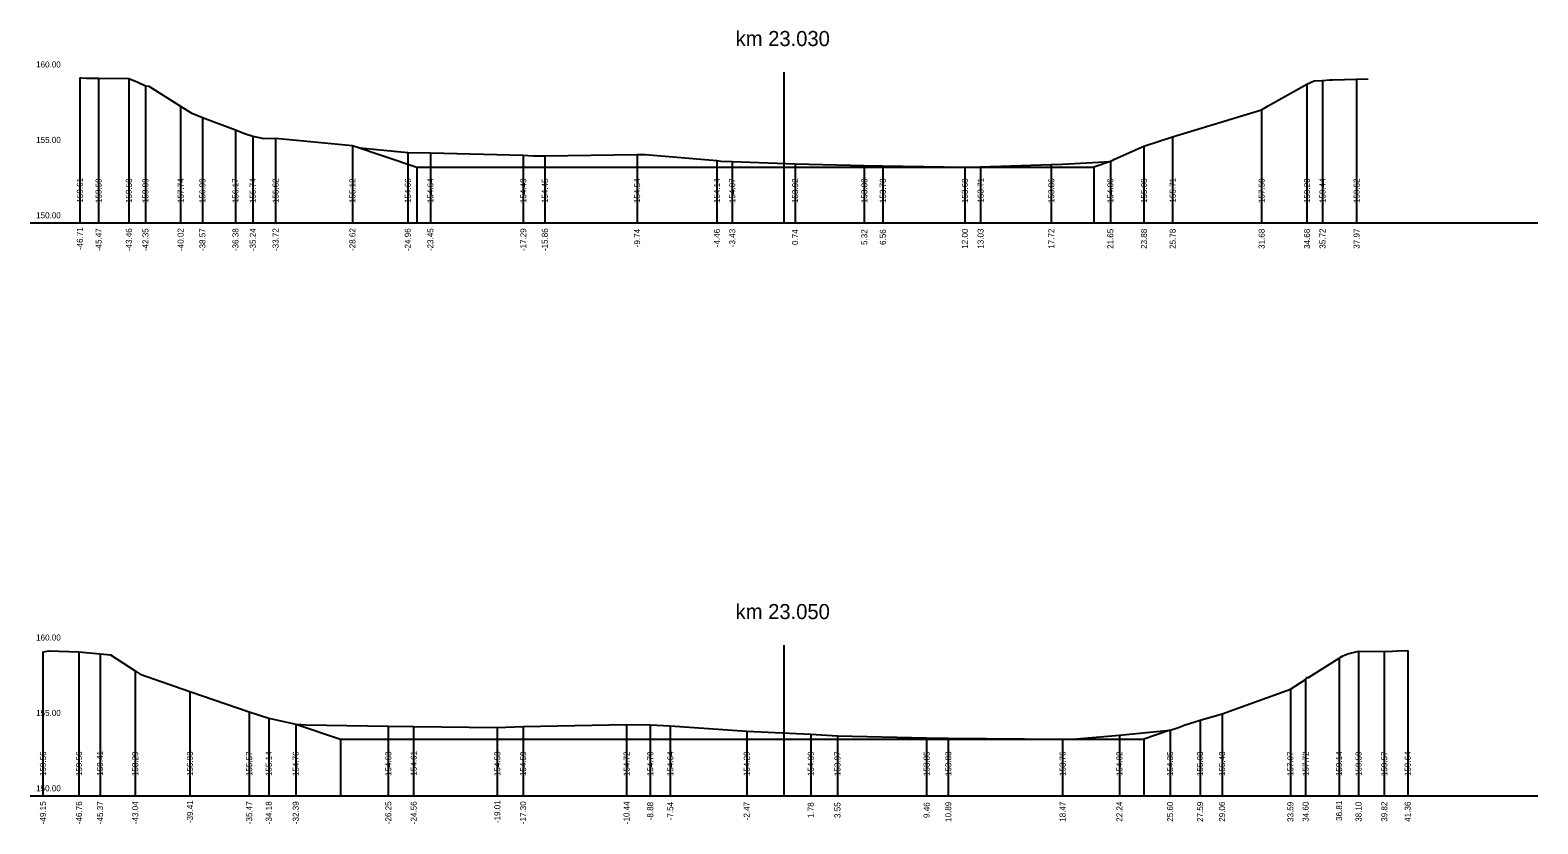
# Model space of a CAD drawing. Extents: x -582678 to -581845, y -1210354 to -1210235.
# Drawn here: x -582165.4 to -582065.4, y -1210306.7 to -1210254.1 of the extents above; entities that cross this region are included whole.
import ezdxf

# ---------------------------------------------------------------- set-up
doc = ezdxf.new("R2010")
doc.units = 0
for name, color, linetype in [('_N_osa', 7, 'Continuous'), ('_N_pomocná', 7, 'Continuous'), ('_N_tučná', 7, 'Continuous'), ('_S_popis', 7, 'Continuous'), ('_S_popis_oprav!', 7, 'Continuous'), ('_S_tenká', 7, 'Continuous'), ('_S_velmi_tenká', 7, 'Continuous')]:
    doc.layers.add(name, color=color, linetype=linetype)

msp = doc.modelspace()

# ---------------------------------------------------------------- linework, layer by layer
at = {"layer": '_N_osa'}
for p, q in [((-582115.45, -1210256.87), (-582115.45, -1210266.87)), ((-582115.45, -1210294.87), (-582115.45, -1210304.87))]:
    msp.add_line(p, q, dxfattribs=at)
at = {"layer": '_N_pomocná'}
for p, q in [((-582139.8, -1210263.17), (-582139.8, -1210266.87)), ((-582094.89, -1210263.17), (-582094.89, -1210266.87)), ((-582144.87, -1210301.1), (-582144.87, -1210304.87)), ((-582091.57, -1210301.1), (-582091.57, -1210304.87))]:
    msp.add_line(p, q, dxfattribs=at)
at = {"layer": '_N_tučná'}
for p, q in [((-582144.07, -1210261.75), (-582139.8, -1210263.17)), ((-582093.8, -1210262.81), (-582094.89, -1210263.17)), ((-582147.83, -1210300.11), (-582144.87, -1210301.1)), ((-582089.84, -1210300.52), (-582091.57, -1210301.1))]:
    msp.add_line(p, q, dxfattribs=at)
for points in [[(-582139.8, -1210263.17), (-582094.89, -1210263.17)], [(-582144.87, -1210301.1), (-582091.57, -1210301.1)]]:
    msp.add_lwpolyline(points, dxfattribs=at)
at = {"layer": '_S_tenká'}
for p, q in [((-582165.45, -1210266.87), (-582065.45, -1210266.87)), ((-582165.45, -1210304.87), (-582065.45, -1210304.87))]:
    msp.add_line(p, q, dxfattribs=at)
for points in [[(-582162.15, -1210257.25), (-582162.07, -1210257.26), (-582161.71, -1210257.27), (-582161.34, -1210257.27), (-582160.91, -1210257.28), (-582158.9, -1210257.29), (-582158.3, -1210257.55), (-582157.8, -1210257.78), (-582157.58, -1210257.81), (-582155.47, -1210259.13), (-582154.87, -1210259.5), (-582154.77, -1210259.58), (-582154.02, -1210259.88), (-582151.83, -1210260.7), (-582151.22, -1210260.94), (-582150.68, -1210261.12), (-582149.94, -1210261.27), (-582149.17, -1210261.25), (-582144.07, -1210261.75), (-582143.57, -1210261.9), (-582140.4, -1210262.2), (-582138.9, -1210262.23), (-582132.74, -1210262.38), (-582132.05, -1210262.43), (-582131.31, -1210262.42), (-582125.19, -1210262.33), (-582124.66, -1210262.35), (-582119.9, -1210262.73), (-582119.63, -1210262.78), (-582118.88, -1210262.8), (-582114.71, -1210262.95), (-582110.12, -1210263.07), (-582108.89, -1210263.09), (-582103.45, -1210263.19), (-582102.41, -1210263.16), (-582097.72, -1210263), (-582096.98, -1210262.98), (-582093.8, -1210262.81), (-582093.52, -1210262.64), (-582091.57, -1210261.79), (-582089.67, -1210261.16), (-582083.77, -1210259.37), (-582083.33, -1210259.11), (-582080.76, -1210257.67), (-582080.28, -1210257.46), (-582079.73, -1210257.43), (-582079.26, -1210257.39), (-582079.06, -1210257.38), (-582077.47, -1210257.35), (-582076.7, -1210257.32)], [(-582164.6, -1210295.31), (-582164.2, -1210295.26), (-582162.21, -1210295.31), (-582160.81, -1210295.46), (-582160.12, -1210295.52), (-582158.48, -1210296.58), (-582158.15, -1210296.8), (-582154.85, -1210297.94), (-582150.92, -1210299.3), (-582149.62, -1210299.72), (-582147.83, -1210300.11), (-582147.16, -1210300.17), (-582141.69, -1210300.24), (-582140.01, -1210300.26), (-582134.46, -1210300.34), (-582132.75, -1210300.28), (-582125.89, -1210300.14), (-582124.32, -1210300.17), (-582122.99, -1210300.23), (-582117.92, -1210300.58), (-582113.67, -1210300.78), (-582111.9, -1210300.9), (-582105.99, -1210301.02), (-582104.55, -1210301.04), (-582096.97, -1210301.11), (-582096.61, -1210301.11), (-582096.28, -1210301.11), (-582093.2, -1210300.84), (-582089.84, -1210300.52), (-582089.28, -1210300.33), (-582088.9, -1210300.18), (-582087.85, -1210299.84), (-582086.39, -1210299.44), (-582081.86, -1210297.79), (-582080.85, -1210297.15), (-582080.77, -1210297.03), (-582080.65, -1210297.02), (-582078.63, -1210295.73), (-582078.39, -1210295.58), (-582078.04, -1210295.45), (-582077.34, -1210295.28), (-582075.63, -1210295.3), (-582075.08, -1210295.28), (-582074.77, -1210295.25), (-582074.08, -1210295.23)]]:
    msp.add_lwpolyline(points, dxfattribs=at)
at = {"layer": '_S_velmi_tenká'}
for points in [[(-582162.15, -1210257.25), (-582162.15, -1210266.87), (-582162.15, -1210266.87), (-582162.15, -1210266.87)], [(-582160.91, -1210257.28), (-582160.91, -1210266.87), (-582160.91, -1210266.87), (-582160.91, -1210266.87)], [(-582158.9, -1210257.29), (-582158.9, -1210266.87), (-582158.9, -1210266.87), (-582158.9, -1210266.87)], [(-582157.8, -1210257.78), (-582157.8, -1210266.87), (-582157.8, -1210266.87), (-582157.8, -1210266.87)], [(-582080.76, -1210257.67), (-582080.76, -1210266.87), (-582080.76, -1210266.87), (-582080.76, -1210266.87)], [(-582079.73, -1210257.43), (-582079.73, -1210266.87), (-582079.73, -1210266.87), (-582079.73, -1210266.87)], [(-582077.47, -1210257.35), (-582077.47, -1210266.87), (-582077.47, -1210266.87), (-582077.47, -1210266.87)], [(-582155.47, -1210259.13), (-582155.47, -1210266.87), (-582155.47, -1210266.87), (-582155.47, -1210266.87)], [(-582154.02, -1210259.88), (-582154.02, -1210266.87), (-582154.02, -1210266.87), (-582154.02, -1210266.87)], [(-582083.77, -1210259.37), (-582083.77, -1210266.87), (-582083.77, -1210266.87), (-582083.77, -1210266.87)], [(-582151.83, -1210260.7), (-582151.83, -1210266.87), (-582151.83, -1210266.87), (-582151.83, -1210266.87)], [(-582150.68, -1210261.12), (-582150.68, -1210266.87), (-582150.68, -1210266.87), (-582150.68, -1210266.87)], [(-582149.17, -1210261.25), (-582149.17, -1210266.87), (-582149.17, -1210266.87), (-582149.17, -1210266.87)], [(-582144.07, -1210261.75), (-582144.07, -1210266.87), (-582144.07, -1210266.87), (-582144.07, -1210266.87)], [(-582091.57, -1210261.79), (-582091.57, -1210266.87), (-582091.57, -1210266.87), (-582091.57, -1210266.87)], [(-582089.67, -1210261.16), (-582089.67, -1210266.87), (-582089.67, -1210266.87), (-582089.67, -1210266.87)], [(-582140.4, -1210262.2), (-582140.4, -1210266.87), (-582140.4, -1210266.87), (-582140.4, -1210266.87)], [(-582138.9, -1210262.23), (-582138.9, -1210266.87), (-582138.9, -1210266.87), (-582138.9, -1210266.87)], [(-582132.74, -1210262.38), (-582132.74, -1210266.87), (-582132.74, -1210266.87), (-582132.74, -1210266.87)], [(-582131.31, -1210262.42), (-582131.31, -1210266.87), (-582131.31, -1210266.87), (-582131.31, -1210266.87)], [(-582125.19, -1210262.33), (-582125.19, -1210266.87), (-582125.19, -1210266.87), (-582125.19, -1210266.87)], [(-582119.9, -1210262.73), (-582119.9, -1210266.87), (-582119.9, -1210266.87), (-582119.9, -1210266.87)], [(-582118.88, -1210262.8), (-582118.88, -1210266.87), (-582118.88, -1210266.87), (-582118.88, -1210266.87)], [(-582114.71, -1210262.95), (-582114.71, -1210266.87), (-582114.71, -1210266.87), (-582114.71, -1210266.87)], [(-582093.8, -1210262.81), (-582093.8, -1210266.87), (-582093.8, -1210266.87), (-582093.8, -1210266.87)], [(-582110.12, -1210263.07), (-582110.12, -1210266.87), (-582110.12, -1210266.87), (-582110.12, -1210266.87)], [(-582108.89, -1210263.09), (-582108.89, -1210266.87), (-582108.89, -1210266.87), (-582108.89, -1210266.87)], [(-582103.45, -1210263.19), (-582103.45, -1210266.87), (-582103.45, -1210266.87), (-582103.45, -1210266.87)], [(-582102.41, -1210263.16), (-582102.41, -1210266.87), (-582102.41, -1210266.87), (-582102.41, -1210266.87)], [(-582097.72, -1210263), (-582097.72, -1210266.87), (-582097.72, -1210266.87), (-582097.72, -1210266.87)], [(-582164.6, -1210295.31), (-582164.6, -1210304.87), (-582164.6, -1210304.87), (-582164.6, -1210304.87)], [(-582162.21, -1210295.31), (-582162.21, -1210304.87), (-582162.21, -1210304.87), (-582162.21, -1210304.87)], [(-582160.81, -1210295.46), (-582160.81, -1210304.87), (-582160.81, -1210304.87), (-582160.81, -1210304.87)], [(-582078.63, -1210295.73), (-582078.63, -1210304.87), (-582078.63, -1210304.87), (-582078.63, -1210304.87)], [(-582077.34, -1210295.28), (-582077.34, -1210304.87), (-582077.34, -1210304.87), (-582077.34, -1210304.87)], [(-582075.63, -1210295.3), (-582075.63, -1210304.87), (-582075.63, -1210304.87), (-582075.63, -1210304.87)], [(-582074.08, -1210295.23), (-582074.08, -1210304.87), (-582074.08, -1210304.87), (-582074.08, -1210304.87)], [(-582158.48, -1210296.58), (-582158.48, -1210304.87), (-582158.48, -1210304.87), (-582158.48, -1210304.87)], [(-582154.85, -1210297.94), (-582154.85, -1210304.87), (-582154.85, -1210304.87), (-582154.85, -1210304.87)], [(-582081.86, -1210297.79), (-582081.86, -1210304.87), (-582081.86, -1210304.87), (-582081.86, -1210304.87)], [(-582080.85, -1210297.15), (-582080.85, -1210304.87), (-582080.85, -1210304.87), (-582080.85, -1210304.87)], [(-582150.92, -1210299.3), (-582150.92, -1210304.87), (-582150.92, -1210304.87), (-582150.92, -1210304.87)], [(-582149.62, -1210299.72), (-582149.62, -1210304.87), (-582149.62, -1210304.87), (-582149.62, -1210304.87)], [(-582087.85, -1210299.84), (-582087.85, -1210304.87), (-582087.85, -1210304.87), (-582087.85, -1210304.87)], [(-582086.39, -1210299.44), (-582086.39, -1210304.87), (-582086.39, -1210304.87), (-582086.39, -1210304.87)], [(-582147.83, -1210300.11), (-582147.83, -1210304.87), (-582147.83, -1210304.87), (-582147.83, -1210304.87)], [(-582141.69, -1210300.24), (-582141.69, -1210304.87), (-582141.69, -1210304.87), (-582141.69, -1210304.87)], [(-582140.01, -1210300.26), (-582140.01, -1210304.87), (-582140.01, -1210304.87), (-582140.01, -1210304.87)], [(-582134.46, -1210300.34), (-582134.46, -1210304.87), (-582134.46, -1210304.87), (-582134.46, -1210304.87)], [(-582132.75, -1210300.28), (-582132.75, -1210304.87), (-582132.75, -1210304.87), (-582132.75, -1210304.87)], [(-582125.89, -1210300.14), (-582125.89, -1210304.87), (-582125.89, -1210304.87), (-582125.89, -1210304.87)], [(-582124.32, -1210300.17), (-582124.32, -1210304.87), (-582124.32, -1210304.87), (-582124.32, -1210304.87)], [(-582122.99, -1210300.23), (-582122.99, -1210304.87), (-582122.99, -1210304.87), (-582122.99, -1210304.87)], [(-582117.92, -1210300.58), (-582117.92, -1210304.87), (-582117.92, -1210304.87), (-582117.92, -1210304.87)], [(-582113.67, -1210300.78), (-582113.67, -1210304.87), (-582113.67, -1210304.87), (-582113.67, -1210304.87)], [(-582111.9, -1210300.9), (-582111.9, -1210304.87), (-582111.9, -1210304.87), (-582111.9, -1210304.87)], [(-582093.2, -1210300.84), (-582093.2, -1210304.87), (-582093.2, -1210304.87), (-582093.2, -1210304.87)], [(-582089.84, -1210300.52), (-582089.84, -1210304.87), (-582089.84, -1210304.87), (-582089.84, -1210304.87)], [(-582105.99, -1210301.02), (-582105.99, -1210304.87), (-582105.99, -1210304.87), (-582105.99, -1210304.87)], [(-582104.55, -1210301.04), (-582104.55, -1210304.87), (-582104.55, -1210304.87), (-582104.55, -1210304.87)], [(-582096.97, -1210301.11), (-582096.97, -1210304.87), (-582096.97, -1210304.87), (-582096.97, -1210304.87)]]:
    msp.add_lwpolyline(points, dxfattribs=at)

# ---------------------------------------------------------------- texts
at = {"layer": '_S_popis'}
for s, p in [('160.00', (-582165.05, -1210256.57)), ('155.00', (-582165.05, -1210261.57)), ('150.00', (-582165.05, -1210266.57)), ('160.00', (-582165.05, -1210294.57)), ('155.00', (-582165.05, -1210299.57)), ('150.00', (-582165.05, -1210304.57))]:
    msp.add_text(s, height=0.4, dxfattribs=at).set_placement(p)
for s, p in [('159.61', (-582161.95, -1210265.53)), ('159.59', (-582160.71, -1210265.56)), ('159.58', (-582158.7, -1210265.56)), ('159.09', (-582157.6, -1210265.56)), ('157.74', (-582155.27, -1210265.56)), ('156.99', (-582153.82, -1210265.56)), ('156.17', (-582151.63, -1210265.56)), ('155.74', (-582150.48, -1210265.56)), ('155.62', (-582148.97, -1210265.56)), ('155.12', (-582143.87, -1210265.56)), ('154.66', (-582140.2, -1210265.56)), ('154.64', (-582138.7, -1210265.56)), ('154.49', (-582132.54, -1210265.56)), ('154.45', (-582131.11, -1210265.56)), ('154.54', (-582124.99, -1210265.56)), ('154.14', (-582119.7, -1210265.56)), ('154.07', (-582118.68, -1210265.56)), ('153.92', (-582114.51, -1210265.56)), ('153.80', (-582109.92, -1210265.56)), ('153.78', (-582108.69, -1210265.56)), ('153.68', (-582103.25, -1210265.56)), ('153.71', (-582102.21, -1210265.53)), ('153.86', (-582097.52, -1210265.56)), ('154.06', (-582093.6, -1210265.56)), ('155.08', (-582091.37, -1210265.56)), ('155.71', (-582089.47, -1210265.53)), ('157.50', (-582083.57, -1210265.56)), ('159.20', (-582080.56, -1210265.56)), ('159.44', (-582079.53, -1210265.56)), ('159.52', (-582077.27, -1210265.56)), ('-46.71', (-582161.95, -1210268.68)), ('-45.47', (-582160.71, -1210268.75)), ('-43.46', (-582158.7, -1210268.75)), ('-42.35', (-582157.6, -1210268.75)), ('-40.02', (-582155.27, -1210268.74)), ('-38.57', (-582153.82, -1210268.75)), ('-36.38', (-582151.63, -1210268.75)), ('-35.24', (-582150.48, -1210268.75)), ('-33.72', (-582148.97, -1210268.74)), ('-28.62', (-582143.87, -1210268.74)), ('-24.96', (-582140.2, -1210268.75)), ('-23.45', (-582138.7, -1210268.75)), ('-17.29', (-582132.54, -1210268.75)), ('-15.86', (-582131.11, -1210268.75)), ('-9.74', (-582124.99, -1210268.49)), ('-4.46', (-582119.7, -1210268.49)), ('-3.43', (-582118.68, -1210268.49)), ('0.74', (-582114.51, -1210268.34)), ('5.32', (-582109.92, -1210268.34)), ('6.56', (-582108.69, -1210268.34)), ('12.00', (-582103.25, -1210268.59)), ('13.03', (-582102.21, -1210268.59)), ('17.72', (-582097.52, -1210268.59)), ('21.65', (-582093.6, -1210268.6)), ('23.88', (-582091.37, -1210268.6)), ('25.78', (-582089.47, -1210268.6)), ('31.68', (-582083.57, -1210268.6)), ('34.68', (-582080.56, -1210268.6)), ('35.72', (-582079.53, -1210268.59)), ('37.97', (-582077.27, -1210268.59)), ('159.56', (-582164.4, -1210303.56)), ('159.56', (-582162.01, -1210303.56)), ('159.41', (-582160.61, -1210303.53)), ('158.29', (-582158.28, -1210303.56)), ('156.93', (-582154.65, -1210303.56)), ('155.57', (-582150.72, -1210303.56)), ('155.14', (-582149.42, -1210303.56)), ('154.76', (-582147.63, -1210303.56)), ('154.63', (-582141.49, -1210303.56)), ('154.61', (-582139.81, -1210303.53)), ('154.53', (-582134.26, -1210303.56)), ('154.59', (-582132.55, -1210303.56)), ('154.72', (-582125.69, -1210303.56)), ('154.70', (-582124.12, -1210303.56)), ('154.64', (-582122.79, -1210303.56)), ('154.29', (-582117.72, -1210303.56)), ('154.09', (-582113.47, -1210303.56)), ('153.97', (-582111.7, -1210303.56)), ('153.85', (-582105.79, -1210303.56)), ('153.83', (-582104.35, -1210303.56)), ('153.76', (-582096.77, -1210303.56)), ('154.02', (-582093, -1210303.56)), ('154.35', (-582089.64, -1210303.56)), ('155.03', (-582087.65, -1210303.56)), ('155.43', (-582086.19, -1210303.56)), ('157.07', (-582081.66, -1210303.56)), ('157.72', (-582080.65, -1210303.56)), ('159.14', (-582078.43, -1210303.56)), ('159.59', (-582077.14, -1210303.56)), ('159.57', (-582075.43, -1210303.56)), ('159.64', (-582073.88, -1210303.56)), ('-49.15', (-582164.4, -1210306.75)), ('-46.76', (-582162.01, -1210306.75)), ('-45.37', (-582160.61, -1210306.75)), ('-43.04', (-582158.28, -1210306.75)), ('-39.41', (-582154.65, -1210306.68)), ('-35.47', (-582150.72, -1210306.75)), ('-34.18', (-582149.42, -1210306.75)), ('-32.39', (-582147.63, -1210306.75)), ('-26.25', (-582141.49, -1210306.75)), ('-24.56', (-582139.81, -1210306.75)), ('-19.01', (-582134.26, -1210306.68)), ('-17.30', (-582132.55, -1210306.75)), ('-10.44', (-582125.69, -1210306.75)), ('-8.88', (-582124.12, -1210306.49)), ('-7.54', (-582122.79, -1210306.49)), ('-2.47', (-582117.72, -1210306.49)), ('1.78', (-582113.47, -1210306.34)), ('3.55', (-582111.7, -1210306.34)), ('9.46', (-582105.79, -1210306.34)), ('10.89', (-582104.35, -1210306.6)), ('18.47', (-582096.77, -1210306.59)), ('22.24', (-582093, -1210306.59)), ('25.60', (-582089.64, -1210306.59)), ('27.59', (-582087.65, -1210306.6)), ('29.06', (-582086.19, -1210306.59)), ('33.59', (-582081.66, -1210306.6)), ('34.60', (-582080.65, -1210306.59)), ('36.81', (-582078.43, -1210306.53)), ('38.10', (-582077.14, -1210306.59)), ('39.82', (-582075.43, -1210306.59)), ('41.36', (-582073.88, -1210306.59))]:
    msp.add_text(s, height=0.4, rotation=90, dxfattribs=at).set_placement(p)
at = {"layer": '_S_popis_oprav!'}
for s, p in [('km 23.030', (-582118.65, -1210255.15)), ('km 23.050', (-582118.65, -1210293.15))]:
    msp.add_text(s, height=1, dxfattribs=at).set_placement(p)

doc.saveas('drawing.dxf')
